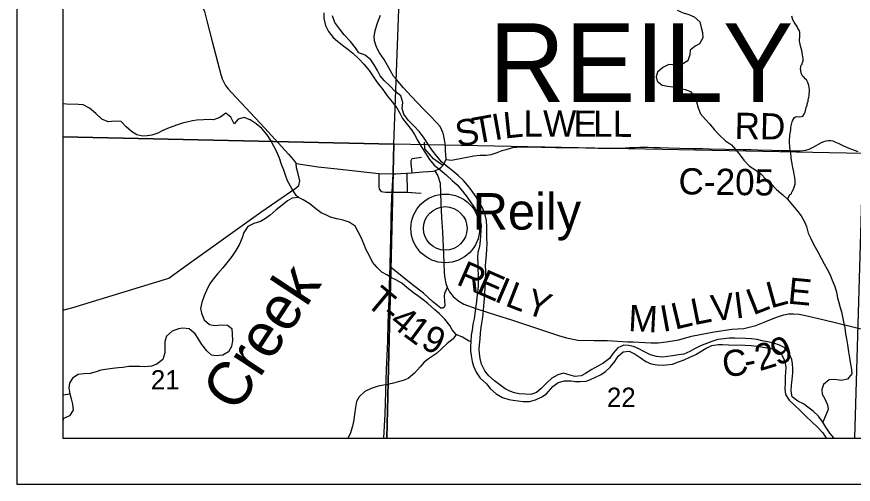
# Model space of a CAD drawing. Extents: x 0 to 34, y 0 to 22.
# Drawn here: x 2 to 3.811, y 14 to 15.013 of the extents above; entities that cross this region are included whole.
import ezdxf

# ---------------------------------------------------------------- set-up
doc = ezdxf.new("R2010")
doc.units = 0
for name, color, linetype in [('Default', 7, 'Continuous'), ('GM_X_County_Road', 7, 'Continuous'), ('GM_X_County_Road_Text', 7, 'Continuous'), ('GM_X_Major_River', 7, 'Continuous'), ('GM_X_Minor_River', 7, 'Continuous'), ('GM_X_Minor_River_Text', 7, 'Continuous'), ('GM_X_Section', 7, 'Continuous'), ('GM_X_Section_Text', 7, 'Continuous'), ('GM_X_State_Route', 7, 'Continuous'), ('GM_X_Township_Road', 7, 'Continuous'), ('GM_X_Township_Road_Text', 7, 'Continuous'), ('GM_X_Township_Text', 7, 'Continuous'), ('GM_X_Unincorporated', 7, 'Continuous'), ('GM_X_Unincorporated_Location', 7, 'Continuous'), ('GM_X_Unincorporated_Text', 7, 'Continuous'), ('SH_Data', 7, 'Continuous')]:
    doc.layers.add(name, color=color, linetype=linetype)

msp = doc.modelspace()

# ---------------------------------------------------------------- linework, layer by layer
at = {"layer": 'Default'}
msp.add_lwpolyline([(5.0396, 17.6997), (4.98, 17.7015), (4.9045, 17.7039), (4.763, 17.7084), (4.6735, 17.7102), (4.6237, 17.7121), (4.506, 17.7155), (4.4203, 17.718), (4.2769, 17.7222), (4.1969, 17.7246), (4.1354, 17.7264), (4.1238, 17.7269), (4.1165, 17.7286), (3.9904, 17.7296), (3.7662, 17.7368), (3.4544, 17.7458), (3.1037, 17.7609), (2.976, 17.7664), (2.8305, 17.7727), (2.1, 17.8044), (2.1, 14.1), (5.898, 14.1)], dxfattribs=at)
for points in [[(2.1, 15.7743), (2.1, 14.7527), (2.8159, 14.7367), (2.854, 15.751)], [(2.1, 14.7527), (2.1, 14.1), (2.801, 14.1), (2.8159, 14.7367)], [(2.801, 14.1), (3.8138, 14.1), (3.832, 14.7167), (2.8159, 14.7367)]]:
    msp.add_lwpolyline(points, close=True, dxfattribs=at)
at = {"layer": 'GM_X_County_Road'}
for points in [[(2.1, 15.2298), (2.1194, 15.2183), (2.2268, 15.1623), (2.3089, 15.1183), (2.3432, 15.1001), (2.3558, 15.0908), (2.3735, 15.0724), (2.3833, 15.0623), (2.3959, 15.0454), (2.4022, 15.0348), (2.4062, 15.0242), (2.4118, 15.0038), (2.4228, 14.9591), (2.4415, 14.8872), (2.4448, 14.878), (2.4486, 14.8705), (2.4521, 14.8639), (2.4576, 14.8562), (2.4645, 14.8488), (2.5372, 14.7709), (2.5879, 14.7152), (2.5984, 14.7036), (2.6047, 14.6945)], [(2.9293, 14.7033), (2.9409, 14.7018), (2.9895, 14.7116), (3.0032, 14.7124), (3.0162, 14.7128), (3.0269, 14.7142), (3.0402, 14.7182), (3.0508, 14.7225), (3.0593, 14.7253), (3.0735, 14.7291), (3.0896, 14.7306), (3.1068, 14.7306), (3.1357, 14.7301), (3.1664, 14.7295), (3.1833, 14.7293), (3.2079, 14.729), (3.2317, 14.7286), (3.2584, 14.7281), (3.3081, 14.728), (3.3267, 14.729), (3.338, 14.7295), (3.3487, 14.7301), (3.3664, 14.7299), (3.3786, 14.7295), (3.3917, 14.729), (3.4104, 14.7287), (3.4351, 14.7282), (3.4647, 14.7274), (3.4846, 14.727), (3.4998, 14.7264), (3.5341, 14.7257), (3.572, 14.7251), (3.5895, 14.7248), (3.6041, 14.7244), (3.6341, 14.7235), (3.6545, 14.7231), (3.6712, 14.7225), (3.684, 14.7222), (3.6956, 14.7221), (3.7079, 14.7238), (3.7155, 14.726), (3.7242, 14.7298), (3.7418, 14.7399), (3.7472, 14.7423), (3.7523, 14.7437), (3.7569, 14.7444), (3.7613, 14.7444), (3.7661, 14.7435), (3.7722, 14.7412), (3.7797, 14.7378), (3.7898, 14.7327), (3.8011, 14.728), (3.809, 14.7251), (3.8203, 14.7206)], [(2.1, 14.3771), (2.1192, 14.3824), (2.3289, 14.4467), (2.3642, 14.4719), (2.5281, 14.5891), (2.5839, 14.6279), (2.6021, 14.6397), (2.6109, 14.6469), (2.6128, 14.6575), (2.609, 14.6723), (2.6057, 14.685), (2.6047, 14.6945), (2.6527, 14.6873), (2.7002, 14.6825), (2.7841, 14.6729), (2.8147, 14.6721)], [(2.9053, 14.6789), (2.9117, 14.6682), (2.9163, 14.652), (2.9179, 14.6097), (2.9194, 14.5769), (2.9214, 14.5464), (2.9241, 14.4806), (2.9252, 14.457), (2.9263, 14.4467), (2.9286, 14.4348), (2.9314, 14.4267), (2.9366, 14.4171), (2.9448, 14.4064), (2.9567, 14.3963), (2.9678, 14.3899), (2.9962, 14.3799), (3.0387, 14.3663), (3.0709, 14.3561), (3.1723, 14.3224), (3.1899, 14.3169), (3.2148, 14.312), (3.2495, 14.3112), (3.2788, 14.3112), (3.3219, 14.3088), (3.334, 14.3083), (3.3598, 14.3069), (3.3734, 14.3061), (3.3883, 14.3066), (3.4057, 14.3081), (3.433, 14.3131), (3.4607, 14.3204), (3.5095, 14.3304), (3.5477, 14.336), (3.5738, 14.3375), (3.5994, 14.3436), (3.6217, 14.3525), (3.6376, 14.3588), (3.6488, 14.3633), (3.6605, 14.3666), (3.6705, 14.3688), (3.6812, 14.3693), (3.6933, 14.3683), (3.7139, 14.3641), (3.7448, 14.3565), (3.81, 14.3408), (3.8603, 14.3289)]]:
    msp.add_lwpolyline(points, dxfattribs=at)
at = {"layer": 'GM_X_Major_River'}
for points in [[(2.6649, 15.0213), (2.665, 15.0084), (2.668, 14.9935), (2.6749, 14.9804), (2.6848, 14.9676), (2.6945, 14.9597), (2.7049, 14.9511), (2.7165, 14.9421), (2.7276, 14.9334), (2.7402, 14.9213), (2.751, 14.91), (2.7628, 14.8964), (2.7712, 14.8833), (2.78, 14.8698), (2.7925, 14.8546), (2.8016, 14.8415), (2.8127, 14.8283), (2.8226, 14.8151), (2.8295, 14.8035), (2.8353, 14.7919), (2.8427, 14.7823), (2.8545, 14.7679), (2.8607, 14.7575), (2.8683, 14.7436), (2.8756, 14.7312), (2.8847, 14.7173), (2.8931, 14.703), (2.9034, 14.6914), (2.9164, 14.6812), (2.9295, 14.6698), (2.9424, 14.6581), (2.9536, 14.6483), (2.9646, 14.6351), (2.9749, 14.6215), (2.9845, 14.6084), (2.9914, 14.5976), (2.9972, 14.5875), (3.003, 14.5737), (3.0049, 14.5599), (3.0046, 14.5497), (3.004, 14.5383), (3.0033, 14.528), (3.0015, 14.5152), (2.9977, 14.5016), (2.9971, 14.4917), (2.9979, 14.4768), (2.9983, 14.4647)], [(3.0455, 14.2152), (3.0343, 14.2238), (3.0217, 14.2348), (3.0132, 14.2453), (3.006, 14.2603), (3.0029, 14.2725), (3.0017, 14.2832), (3.0011, 14.2927), (3.0014, 14.3022), (3.0029, 14.3151), (3.0039, 14.3269), (3.0054, 14.3394), (3.0064, 14.3489), (3.0086, 14.3617), (3.0101, 14.3761), (3.0111, 14.3864), (3.0123, 14.402), (3.013, 14.4149), (3.0136, 14.4255), (3.0143, 14.4354), (3.015, 14.4627), (3.0148, 14.4726), (3.0155, 14.4825), (3.0166, 14.4962), (3.0173, 14.5098), (3.0179, 14.5197), (3.0175, 14.5334), (3.0174, 14.5433), (3.0174, 14.5574), (3.0166, 14.5711), (3.0142, 14.5837), (3.0089, 14.5971), (3.0023, 14.6091), (2.9947, 14.6226), (2.9833, 14.6377), (2.9756, 14.6481), (2.9671, 14.6579), (2.9552, 14.6688), (2.9426, 14.6794), (2.9329, 14.6868), (2.9203, 14.6978), (2.9088, 14.711), (2.8986, 14.7242), (2.8901, 14.7373), (2.8821, 14.7493), (2.8718, 14.7633), (2.8592, 14.7765), (2.847, 14.7882), (2.8382, 14.8014), (2.834, 14.8137), (2.8358, 14.8269), (2.8313, 14.8411), (2.8186, 14.8517), (2.809, 14.8611), (2.7953, 14.8743), (2.7864, 14.8848), (2.7806, 14.896), (2.7737, 14.9083), (2.7668, 14.9191), (2.7541, 14.929), (2.7406, 14.9346), (2.7336, 14.9451), (2.7222, 14.9587), (2.7089, 14.9731), (2.6993, 14.9855), (2.6883, 15.0002), (2.6834, 15.0144)], [(2.9983, 14.4647), (2.9988, 14.454), (2.9989, 14.4441), (2.9986, 14.4304), (2.998, 14.4209), (2.9966, 14.4111), (2.995, 14.3955), (2.9931, 14.3807), (2.9917, 14.3701), (2.9899, 14.3584), (2.9873, 14.347), (2.9855, 14.3338), (2.9837, 14.3228), (2.9826, 14.3088), (2.9823, 14.2981), (2.9824, 14.2882), (2.9833, 14.2787), (2.9856, 14.2657), (2.9884, 14.2554), (2.9942, 14.2431), (3.0033, 14.2295), (3.0167, 14.2178), (3.0255, 14.2069), (3.0378, 14.1956), (3.0516, 14.188), (3.0648, 14.1835), (3.0747, 14.1822), (3.0856, 14.1804), (3.0959, 14.1794), (3.1099, 14.179), (3.1229, 14.1825), (3.1364, 14.1894), (3.1464, 14.196), (3.1601, 14.212), (3.1717, 14.2204), (3.1855, 14.2239), (3.1999, 14.2239), (3.2097, 14.2225), (3.2196, 14.2223), (3.2322, 14.2235), (3.2421, 14.2267), (3.2525, 14.2318), (3.2648, 14.2379), (3.2745, 14.2445), (3.2846, 14.2538), (3.2948, 14.2661), (3.3019, 14.2777), (3.3128, 14.2865), (3.3253, 14.2881), (3.3385, 14.2814), (3.3497, 14.2742), (3.362, 14.2659), (3.3733, 14.2611), (3.3865, 14.2585), (3.3994, 14.2582), (3.4057, 14.2585)], [(3.7692, 14.1), (3.7684, 14.1009), (3.7602, 14.111), (3.751, 14.1233), (3.7451, 14.1345), (3.7355, 14.1472), (3.7236, 14.1585), (3.7124, 14.1671), (3.7026, 14.1741), (3.6906, 14.1801), (3.6783, 14.1894), (3.6759, 14.2017), (3.6769, 14.2149), (3.6783, 14.2271), (3.6797, 14.2411), (3.6799, 14.2506), (3.679, 14.2605), (3.6777, 14.2704), (3.6722, 14.2831), (3.6626, 14.2954), (3.6513, 14.301), (3.6385, 14.3054), (3.6253, 14.3084), (3.6135, 14.3105), (3.6029, 14.3134), (3.5904, 14.3152), (3.5772, 14.3158), (3.554, 14.3163), (3.5418, 14.3162), (3.5304, 14.3153), (3.5178, 14.3132), (3.5044, 14.3089), (3.4799, 14.2996), (3.4669, 14.293), (3.4572, 14.2875), (3.4442, 14.282), (3.4324, 14.2804), (3.4194, 14.278), (3.3975, 14.275)], [(3.3975, 14.275), (3.3847, 14.2768), (3.3715, 14.2802), (3.3587, 14.2866), (3.3449, 14.2941), (3.3351, 14.2982), (3.3238, 14.3003), (3.3139, 14.301), (3.3012, 14.2956), (3.2911, 14.284), (3.2828, 14.2721), (3.2689, 14.2618), (3.2577, 14.256), (3.245, 14.2487), (3.2311, 14.2399), (3.2215, 14.2348), (3.2078, 14.2336), (3.1979, 14.2361), (3.1832, 14.2403), (3.171, 14.2372), (3.1579, 14.2295), (3.1474, 14.2195), (3.1345, 14.2065), (3.1248, 14.1988), (3.113, 14.1945), (3.1004, 14.1948), (3.0875, 14.1955), (3.0777, 14.1977), (3.0672, 14.2017), (3.0571, 14.2069), (3.0455, 14.2152)], [(3.4057, 14.2585), (3.4194, 14.2601), (3.4324, 14.2648), (3.4447, 14.2695), (3.4566, 14.2753), (3.4696, 14.2808), (3.4793, 14.287), (3.4923, 14.2944), (3.5043, 14.3006), (3.5184, 14.303), (3.5279, 14.3028), (3.5404, 14.3021), (3.5765, 14.3014), (3.5894, 14.3004), (3.6019, 14.2993), (3.6155, 14.2968), (3.6284, 14.295), (3.6416, 14.2924), (3.6529, 14.2854), (3.6606, 14.2719), (3.6631, 14.2624), (3.6644, 14.2528), (3.6642, 14.2426), (3.6636, 14.2327), (3.6629, 14.2194), (3.6627, 14.2069), (3.6643, 14.1943), (3.6716, 14.182), (3.6836, 14.1711), (3.6959, 14.1598), (3.7089, 14.147), (3.7208, 14.135), (3.7335, 14.1237), (3.745, 14.1113), (3.7518, 14.1)]]:
    msp.add_lwpolyline(points, dxfattribs=at)
at = {"layer": 'GM_X_Minor_River'}
for points in [[(3.4297, 15.0269), (3.4425, 15.0213), (3.4546, 15.0177), (3.4662, 15.0122), (3.4782, 15.0013), (3.4814, 14.9891), (3.4842, 14.9784), (3.4848, 14.967), (3.4781, 14.9542), (3.4681, 14.949), (3.4577, 14.9401), (3.4568, 14.9298), (3.4528, 14.917), (3.4397, 14.9089), (3.4275, 14.9075)], [(3.6686, 14.6174), (3.6724, 14.6251), (3.6736, 14.6274), (3.6767, 14.6292), (3.6771, 14.6315), (3.6783, 14.6341), (3.6815, 14.639), (3.6823, 14.6412), (3.6843, 14.6476), (3.6848, 14.6499), (3.6849, 14.6579), (3.6839, 14.664), (3.6833, 14.6678), (3.6829, 14.6709), (3.6819, 14.6766), (3.6812, 14.6793), (3.6799, 14.6861), (3.6792, 14.6888), (3.6782, 14.6949), (3.6775, 14.6984), (3.6765, 14.706), (3.6759, 14.7098), (3.6746, 14.7212), (3.6732, 14.7289), (3.673, 14.7335), (3.6723, 14.738), (3.6725, 14.746), (3.673, 14.7528), (3.6735, 14.7563), (3.6753, 14.7676), (3.6758, 14.7722), (3.6762, 14.776), (3.6783, 14.7847), (3.6799, 14.7884), (3.6835, 14.7944), (3.6858, 14.7955), (3.6885, 14.7962), (3.6946, 14.796), (3.6984, 14.7963), (3.7018, 14.7974), (3.705, 14.803), (3.7062, 14.806), (3.7087, 14.8158), (3.7107, 14.8211), (3.7112, 14.8241), (3.7128, 14.8294), (3.7129, 14.8321), (3.7145, 14.8385), (3.7154, 14.8411), (3.7157, 14.8548), (3.7144, 14.8636), (3.7129, 14.8678), (3.7126, 14.8701), (3.7112, 14.8732), (3.7093, 14.8759), (3.7067, 14.8782), (3.7045, 14.881), (3.7015, 14.8833), (3.6997, 14.886), (3.6979, 14.8902), (3.6969, 14.8967), (3.6965, 14.899), (3.6974, 14.9047), (3.6982, 14.9073), (3.7002, 14.9096), (3.701, 14.9134), (3.7019, 14.9168), (3.7023, 14.919), (3.702, 14.9221), (3.7017, 14.9266), (3.701, 14.9293), (3.6997, 14.9358), (3.699, 14.9393), (3.6972, 14.9465), (3.6962, 14.9496), (3.6952, 14.9568), (3.6945, 14.9595), (3.6946, 14.9637), (3.6951, 14.9675), (3.6952, 14.974), (3.6949, 14.9781), (3.6939, 14.9835), (3.6909, 14.9874), (3.6891, 14.9912), (3.6854, 14.9963), (3.6825, 15.0009), (3.6796, 15.0059), (3.6779, 15.0136)], [(3.4275, 14.9075), (3.4113, 14.909), (3.3983, 14.9028), (3.387, 14.8928), (3.3837, 14.8826), (3.3861, 14.8727), (3.3969, 14.8641), (3.409, 14.8619), (3.4204, 14.8608)], [(3.4204, 14.8608), (3.4467, 14.8551), (3.4584, 14.8504), (3.4669, 14.8392), (3.4716, 14.8281), (3.4748, 14.8155), (3.4799, 14.8021), (3.4907, 14.7897), (3.5, 14.7797), (3.5093, 14.7681), (3.5205, 14.7565), (3.5343, 14.7441), (3.5474, 14.7351), (3.5559, 14.7247), (3.5656, 14.7124), (3.5741, 14.7016), (3.586, 14.6892), (3.5995, 14.6806), (3.6104, 14.672), (3.6216, 14.6604), (3.6317, 14.6519), (3.6447, 14.6387), (3.6581, 14.6267), (3.6686, 14.6174), (3.6794, 14.6043), (3.6898, 14.5912), (3.6976, 14.5811), (3.7053, 14.5681), (3.7093, 14.5585), (3.7128, 14.5436), (3.7191, 14.5321), (3.7256, 14.5183), (3.7341, 14.5033), (3.7414, 14.4895), (3.7477, 14.4776), (3.7543, 14.4661), (3.7609, 14.4534), (3.7649, 14.4423), (3.7707, 14.4286), (3.7743, 14.4163), (3.7767, 14.4037), (3.7795, 14.3934), (3.7824, 14.3827), (3.7849, 14.3732), (3.787, 14.3625), (3.7901, 14.3484), (3.7922, 14.3385), (3.7939, 14.3259), (3.796, 14.3148), (3.798, 14.3019), (3.8004, 14.287), (3.8024, 14.2741), (3.8048, 14.26), (3.8065, 14.2485), (3.8075, 14.239), (3.7985, 14.2274), (3.7845, 14.225), (3.7708, 14.2271), (3.7583, 14.2262), (3.746, 14.2161), (3.7424, 14.2052), (3.7433, 14.1949), (3.7488, 14.1853), (3.755, 14.1719), (3.7564, 14.162), (3.7451, 14.1345)], [(2.61, 14.621), (2.6048, 14.6253), (2.5957, 14.6404), (2.5862, 14.657), (2.5827, 14.667), (2.5781, 14.6804), (2.5734, 14.6923), (2.5688, 14.7065), (2.562, 14.7215), (2.5562, 14.7323), (2.5497, 14.7446), (2.5424, 14.7566), (2.5306, 14.7706), (2.5183, 14.7804), (2.5056, 14.7894), (2.4925, 14.7943), (2.4795, 14.7905), (2.4709, 14.7808), (2.4632, 14.7947), (2.4524, 14.8037), (2.4393, 14.7941), (2.4259, 14.7895), (2.4164, 14.7897), (2.4046, 14.7896), (2.3898, 14.7885), (2.3802, 14.7868), (2.3684, 14.7844), (2.3585, 14.782), (2.3478, 14.7785), (2.3378, 14.7746), (2.3263, 14.7707), (2.3163, 14.766), (2.3055, 14.7605), (2.2925, 14.7563), (2.2826, 14.7546), (2.2727, 14.7541), (2.2602, 14.7567), (2.2483, 14.7642), (2.2371, 14.7744), (2.2257, 14.7857), (2.212, 14.7864), (2.1979, 14.7848), (2.184, 14.7909), (2.171, 14.803), (2.1576, 14.8144), (2.1438, 14.8215), (2.1335, 14.8226), (2.1077, 14.8232), (2.1, 14.824)], [(2.9826, 14.3088), (2.9777, 14.3104), (2.9646, 14.3183), (2.9511, 14.3244), (2.9422, 14.3341), (2.9375, 14.3441), (2.9268, 14.3577), (2.9154, 14.3694), (2.9053, 14.378), (2.8897, 14.3917), (2.8797, 14.3991), (2.8685, 14.4078), (2.8588, 14.4149), (2.8454, 14.4251), (2.8335, 14.4356), (2.8208, 14.4424), (2.811, 14.4472), (2.8009, 14.4536), (2.7904, 14.4595), (2.7801, 14.4697), (2.7701, 14.4813), (2.7632, 14.4944), (2.7564, 14.5079), (2.7514, 14.5209), (2.7456, 14.5344), (2.7387, 14.5467), (2.7322, 14.5591), (2.7199, 14.5674), (2.7063, 14.5719), (2.6931, 14.5749), (2.6795, 14.5786), (2.669, 14.5834), (2.6593, 14.5879), (2.6473, 14.5965), (2.6343, 14.6071), (2.6201, 14.6162), (2.61, 14.621), (2.5963, 14.6199), (2.5859, 14.614), (2.5742, 14.6048), (2.5614, 14.5941), (2.5486, 14.5826), (2.5386, 14.5753), (2.5274, 14.5691), (2.5132, 14.5649), (2.5001, 14.558), (2.4915, 14.5452), (2.4877, 14.5335), (2.4825, 14.52), (2.4745, 14.5061), (2.4655, 14.493), (2.4576, 14.4829), (2.4459, 14.4688), (2.4353, 14.4565), (2.4271, 14.4468), (2.4176, 14.433), (2.4104, 14.4199), (2.4056, 14.4078), (2.4007, 14.3939), (2.398, 14.381), (2.4001, 14.3707), (2.4054, 14.3561), (2.4173, 14.3459), (2.4286, 14.3437), (2.442, 14.3453), (2.456, 14.3446), (2.4657, 14.3375), (2.4661, 14.3253), (2.4669, 14.3112), (2.4651, 14.2983), (2.4587, 14.2871), (2.446, 14.2794), (2.4319, 14.2779), (2.4217, 14.2793), (2.4113, 14.2887), (2.401, 14.303), (2.3926, 14.3157), (2.386, 14.3258), (2.3734, 14.3364), (2.3597, 14.3382), (2.3502, 14.3369), (2.3364, 14.3312), (2.324, 14.3205), (2.3206, 14.3091), (2.3207, 14.297), (2.3204, 14.2844), (2.3159, 14.2705), (2.3035, 14.2601), (2.2919, 14.2559), (2.2775, 14.2543), (2.2665, 14.255), (2.2547, 14.2553), (2.2429, 14.2548), (2.23, 14.2528), (2.2205, 14.2523), (2.2075, 14.2507), (2.1972, 14.2495), (2.1823, 14.2468), (2.1716, 14.2436), (2.159, 14.2401), (2.1449, 14.239)], [(2.9511, 14.3244), (2.9444, 14.315), (2.9316, 14.3051), (2.9187, 14.2925), (2.9086, 14.2832), (2.8936, 14.2733), (2.8816, 14.2645), (2.8733, 14.254), (2.8612, 14.2407), (2.8472, 14.2288), (2.8365, 14.2245), (2.8254, 14.2218), (2.8158, 14.219), (2.8063, 14.2165), (2.7948, 14.2145), (2.7826, 14.2122), (2.7673, 14.2076), (2.7535, 14.2007), (2.741, 14.1893), (2.7355, 14.1791), (2.7336, 14.1666), (2.7313, 14.1515), (2.7295, 14.1397), (2.7269, 14.1261), (2.7215, 14.1095), (2.7166, 14.1)], [(2.1449, 14.239), (2.1331, 14.2377), (2.1204, 14.2297), (2.1144, 14.2188), (2.113, 14.209), (2.1146, 14.196), (2.1181, 14.1849), (2.1209, 14.1738), (2.1221, 14.1608), (2.1145, 14.1485), (2.1015, 14.1427), (2.1, 14.137)], [(2.1146, 14.196), (2.1096, 14.1946), (2.1, 14.1928)]]:
    msp.add_lwpolyline(points, dxfattribs=at)
at = {"layer": 'GM_X_Section'}
msp.add_lwpolyline([(2.854, 15.751), (3.8671, 15.713), (3.832, 14.7167), (2.8159, 14.7367)], close=True, dxfattribs=at)
at = {"layer": 'GM_X_State_Route'}
for points in [[(2.922, 14.7621), (2.9204, 14.7669), (2.9163, 14.7746), (2.9088, 14.7836), (2.8947, 14.7979), (2.8804, 14.8122), (2.8547, 14.8398), (2.8373, 14.8583), (2.821, 14.8776), (2.8156, 14.884), (2.8089, 14.8954), (2.7952, 14.9199), (2.7853, 14.9347), (2.7801, 14.9438), (2.777, 14.951), (2.7747, 14.9602), (2.7739, 14.9696), (2.7757, 14.9818), (2.7801, 14.9975), (2.7876, 15.016)], [(2.9293, 14.7033), (2.9291, 14.714), (2.9284, 14.7218), (2.9279, 14.7334), (2.9266, 14.7421), (2.9255, 14.7492), (2.9242, 14.7544), (2.9227, 14.7602), (2.922, 14.7621)], [(2.8206, 14.6724), (2.8315, 14.6729), (2.8445, 14.6741), (2.8556, 14.6748), (2.878, 14.6765), (2.8911, 14.6775), (2.901, 14.6784), (2.9053, 14.6789), (2.9143, 14.6832), (2.9184, 14.6866), (2.9222, 14.6906), (2.9253, 14.6953), (2.9293, 14.7033)], [(2.8084, 14.4769), (2.8099, 14.5347), (2.8104, 14.5658), (2.8107, 14.5814), (2.8112, 14.5981), (2.8121, 14.623), (2.8128, 14.6324), (2.8147, 14.6721), (2.8206, 14.6724)], [(2.7949, 14.1), (2.796, 14.1266), (2.7975, 14.1515), (2.8005, 14.2487), (2.8017, 14.2787), (2.8029, 14.31), (2.8037, 14.3511), (2.8052, 14.3784), (2.8064, 14.4099), (2.8068, 14.4282), (2.8077, 14.454), (2.8082, 14.4709), (2.8084, 14.4769)]]:
    msp.add_lwpolyline(points, dxfattribs=at)
at = {"layer": 'GM_X_Township_Road'}
msp.add_line((2.8445, 14.6741), (2.8452, 14.6326), dxfattribs=at)
for points in [[(2.9222, 14.6906), (2.9022, 14.7047), (2.8833, 14.7267), (2.8824, 14.7408)], [(2.8556, 14.6748), (2.8546, 14.6885), (2.8539, 14.695), (2.8535, 14.7009), (2.8558, 14.7055), (2.8607, 14.7064), (2.8761, 14.7082)], [(2.7841, 14.6729), (2.7836, 14.6528), (2.7835, 14.6446), (2.7848, 14.6389), (2.7889, 14.6342), (2.7983, 14.6325), (2.8128, 14.6324)], [(2.8128, 14.6324), (2.8452, 14.6326), (2.8536, 14.6316), (2.8543, 14.6316)], [(2.8543, 14.6316), (2.8638, 14.6311), (2.8752, 14.6307)], [(2.9314, 14.4267), (2.9291, 14.4192), (2.9258, 14.4141), (2.9252, 14.4077), (2.9266, 14.3868), (2.9255, 14.3837), (2.922, 14.3815), (2.9179, 14.3811), (2.9, 14.3959), (2.8806, 14.4142), (2.8569, 14.4321), (2.8082, 14.4709)]]:
    msp.add_lwpolyline(points, dxfattribs=at)
at = {"layer": 'GM_X_Unincorporated'}
for radius in [0.0744, 0.0472]:
    msp.add_circle((2.9275, 14.554), radius, dxfattribs=at)
at = {"layer": 'GM_X_Unincorporated_Location'}
msp.add_line((2.9275, 14.554), (2.9275, 14.554), dxfattribs=at)
at = {"layer": 'SH_Data'}
for p, q in [((2, 21), (2, 14)), ((2.1, 20.9), (2.1, 14.1)), ((2.1, 14.1), (8.9, 14.1)), ((2.1, 14.1), (2.1, 14.1)), ((2, 14), (9, 14))]:
    msp.add_line(p, q, dxfattribs=at)

# ---------------------------------------------------------------- texts
at = {"layer": 'GM_X_County_Road_Text'}
for s, height, rotation, p in [('S', 0.0568, 10.2657, (2.9546, 14.7302)), ('T', 0.0568, 10.2588, (2.9923, 14.7371)), ('I', 0.0568, 10.0666, (3.0341, 14.7446)), ('L', 0.0568, 5.9376, (3.056, 14.7486)), ('L', 0.0568, 0.0771, (3.0968, 14.7529)), ('W', 0.0568, 359.8229, (3.1392, 14.7529)), ('E', 0.0568, 359.82, (3.205, 14.7527)), ('L', 0.0568, 359.82, (3.2475, 14.7526)), ('L', 0.0568, 359.8212, (3.29, 14.7525)), ('RD', 0.05682, 359.0113, (3.5534, 14.7481)), ('C-205', 0.05682, 359.2071, (3.4321, 14.628)), ('R', 0.0568, 336.2769, (2.9493, 14.4337)), ('E', 0.0568, 336.2874, (2.992, 14.4149)), ('I', 0.0568, 336.8025, (3.0314, 14.3976)), ('L', 0.0568, 338.8058, (3.0548, 14.3876)), ('L', 0.0568, 15.4073, (3.6319, 14.3806)), ('E', 0.0568, 354.6395, (3.6674, 14.3914)), ('Y', 0.0568, 341.5733, (3.0972, 14.3713)), ('V', 0.0568, 6.9749, (3.5061, 14.3526)), ('I', 0.0568, 7.2675, (3.556, 14.3587)), ('L', 0.0568, 21.5857, (3.5939, 14.3654)), ('L', 0.0568, 11.2883, (3.4655, 14.3444)), ('M', 0.0568, 357.0333, (3.3228, 14.332)), ('I', 0.0568, 10.2626, (3.3984, 14.3297)), ('L', 0.0568, 13.5399, (3.4248, 14.3346)), ('2', 0.0568, 17.1242, (3.608, 14.2446)), ('9', 0.0568, 20.9859, (3.6452, 14.2562)), ('C', 0.0568, 10.044, (3.5323, 14.2302)), ('-', 0.0568, 11.4002, (3.5794, 14.2385))]:
    msp.add_text(s, height=height, rotation=rotation, dxfattribs=at).set_placement(p)
at = {"layer": 'GM_X_Minor_River_Text'}
msp.add_text('Creek', height=0.09472, rotation=56.6115, dxfattribs=at).set_placement((2.4754, 14.1524))
at = {"layer": 'GM_X_Section_Text'}
for s, p in [('21', (2.2903, 14.2053)), ('22', (3.2774, 14.1674))]:
    msp.add_text(s, height=0.04186, rotation=0, dxfattribs=at).set_placement(p)
at = {"layer": 'GM_X_Township_Road_Text'}
for s, rotation, p in [('T', 320.1156, (2.7529, 14.3901)), ('-', 320.273, (2.7856, 14.3627)), ('4', 320.9949, (2.8041, 14.3473)), ('1', 323.6813, (2.8336, 14.3235)), ('9', 334.5829, (2.8719, 14.2967))]:
    msp.add_text(s, height=0.0568, rotation=rotation, dxfattribs=at).set_placement(p)
at = {"layer": 'GM_X_Township_Text'}
msp.add_text('REILY', height=0.17045, rotation=0, dxfattribs=at).set_placement((3.022, 14.8278))
at = {"layer": 'GM_X_Unincorporated_Text'}
msp.add_text('Reily', height=0.07898, rotation=0, dxfattribs=at).set_placement((2.9869, 14.5515))

doc.saveas('drawing.dxf')
